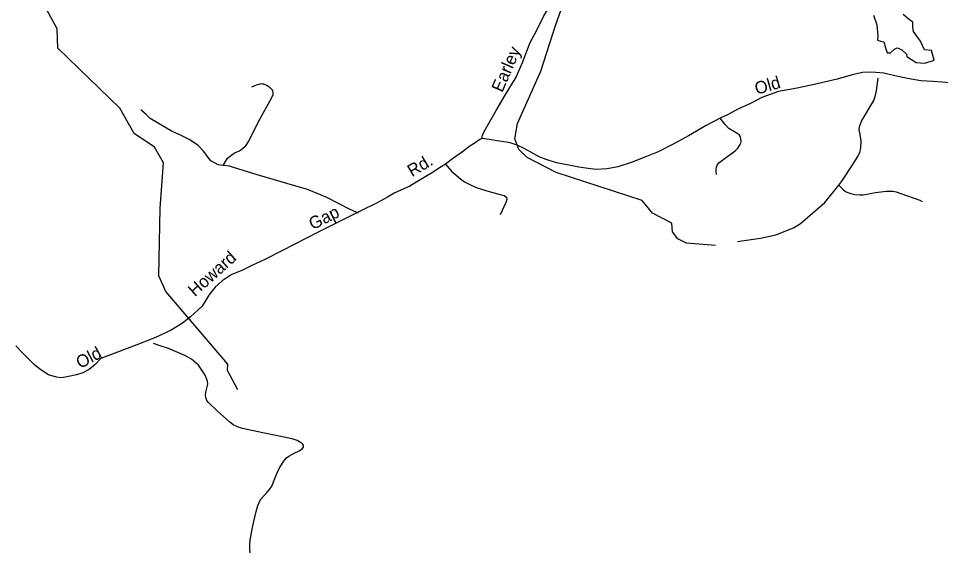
# Model space of a CAD drawing. Extents: x 990631 to 1056237, y 535999 to 585651.
# Drawn here: x 1014890 to 1021960, y 555422 to 559461 of the extents above; entities that cross this region are included whole.
import ezdxf

# ---------------------------------------------------------------- set-up
doc = ezdxf.new("R2010")
doc.units = 0
for name, color, linetype in [('Exist Hydrographic Creek Single Shore', 7, 'Continuous'), ('Exist Hydrographic Pond Over 1500 Sq Ft', 7, 'Continuous'), ('Exist Road Non-System Type 51', 7, 'Continuous'), ('Exist Road Secondary Type 41 Attributed', 7, 'Continuous'), ('Exist Road Secondary Type 51 Attributed', 7, 'Continuous'), ('Exist Road Secondary Type 51 Label', 7, 'Continuous')]:
    doc.layers.add(name, color=color, linetype=linetype)

msp = doc.modelspace()

# ---------------------------------------------------------------- linework, layer by layer
at = {"layer": 'Exist Hydrographic Creek Single Shore'}
for points in [[(1016571.4, 556616.2), (1016492.9, 556762.2), (1016494.5, 556811.4), (1016021.2, 557369), (1015966.6, 557488.3), (1015975.7, 558006.6), (1016003.6, 558354), (1015932.7, 558473.5), (1015777.9, 558578.4), (1015667.7, 558774.2), (1015191, 559233.5), (1015187.6, 559381.3), (1015109.1, 559527.2), (1015083.9, 559770.6), (1014986.1, 560090.9), (1014907.6, 560243.5), (1014912.8, 560391), (1015271.4, 560895.8), (1015405.6, 561168.8), (1015417.6, 561276.8), (1015082.1, 561720), (1014955.8, 561912.5), (1014924.7, 562002.2)], [(1016571.4, 556616.2), (1016492.9, 556762.2), (1016494.5, 556811.4), (1016021.2, 557369), (1015966.6, 557488.3), (1015975.7, 558006.6), (1016003.6, 558354), (1015932.7, 558473.5), (1015777.9, 558578.4), (1015667.7, 558774.2), (1015191, 559233.5), (1015187.6, 559381.3), (1015109.1, 559527.2), (1015083.9, 559770.6), (1014986.1, 560090.9), (1014907.6, 560243.5), (1014912.8, 560391), (1015271.4, 560895.8), (1015405.6, 561168.8), (1015417.6, 561276.8), (1015082.1, 561720), (1014955.8, 561912.5), (1014924.7, 562002.2)], [(1020235.4, 557720.5), (1020011, 557738.2), (1019945.4, 557772.3), (1019905.5, 557825.6), (1019899.3, 557891.4), (1019751.9, 557969.8), (1019671.6, 558066.6), (1019011.7, 558280.1), (1018790.5, 558396.1), (1018725.7, 558456.6), (1018695.2, 558539.2), (1018715.7, 558657), (1018895.9, 559057), (1019007.6, 559405.9), (1019191.5, 559924)], [(1020235.4, 557720.5), (1020011, 557738.2), (1019945.4, 557772.3), (1019905.5, 557825.6), (1019899.3, 557891.4), (1019751.9, 557969.8), (1019671.6, 558066.6), (1019011.7, 558280.1), (1018790.5, 558396.1), (1018725.7, 558456.6), (1018695.2, 558539.2), (1018715.7, 558657), (1018895.9, 559057), (1019007.6, 559405.9), (1019191.5, 559924)]]:
    msp.add_lwpolyline(points, dxfattribs=at)
at = {"layer": 'Exist Hydrographic Pond Over 1500 Sq Ft'}
msp.add_lwpolyline([(1021446.8, 559486.9), (1021471.9, 559411.6), (1021480.3, 559323.8), (1021476.1, 559294.5), (1021501.2, 559286.2), (1021526.3, 559282), (1021538.8, 559236), (1021551.3, 559198.3), (1021576.4, 559198.3), (1021609.9, 559227.6), (1021630.8, 559236), (1021664.2, 559219.2), (1021697.6, 559185.8), (1021701.8, 559169.1), (1021772.9, 559123.1), (1021839.8, 559118.9), (1021910.8, 559139.8), (1021898.3, 559185.8), (1021889.9, 559215.1), (1021835.6, 559219.2), (1021806.3, 559286.2), (1021752, 559361.4), (1021747.8, 559394.9), (1021747.8, 559432.5), (1021722.7, 559449.2), (1021672.6, 559491.1)], dxfattribs=at)
at = {"layer": 'Exist Road Non-System Type 51'}
for points in [[(1016459.9, 558333.8), (1016491.8, 558390.8), (1016547.3, 558431.1), (1016583.8, 558445.7), (1016633, 558484.2), (1016656.3, 558521.5), (1016707.8, 558623.9), (1016741.9, 558688.6), (1016805.9, 558804.6), (1016833.5, 558855.8), (1016842.3, 558877.5), (1016842.9, 558893.5), (1016839.4, 558907.5), (1016831.6, 558917.9), (1016820, 558928.3), (1016804.4, 558938.9), (1016794.5, 558947.1), (1016770.9, 558955.9), (1016759, 558958.4), (1016749, 558958.6), (1016732.9, 558955.3), (1016712.6, 558949.9), (1016678.1, 558935)], [(1021180, 558184.3), (1021203, 558213.7), (1021283.1, 558335.1), (1021325.3, 558403.7), (1021342.6, 558441.1), (1021347.7, 558473), (1021351.2, 558520.8), (1021342.8, 558571.2), (1021336.2, 558607.5), (1021338.8, 558629.3), (1021354.3, 558674.8), (1021375.7, 558712.1), (1021426.4, 558794.6), (1021447.7, 558831.9), (1021458.8, 558863.5), (1021468.2, 558905.1), (1021481.4, 559002.9)], [(1016459.9, 558333.8), (1016422, 558339.2), (1016398.4, 558351.9), (1016365, 558369.1), (1016343.9, 558395.8), (1016326.8, 558420.3), (1016305.5, 558445.2), (1016266.9, 558486.4), (1016204.4, 558530.4), (1016127.5, 558569.2), (1016068.4, 558595.2), (1015899.6, 558694.8), (1015868.6, 558723.9), (1015827.7, 558759.3)], [(1020242, 558265.7), (1020238.9, 558289.7), (1020239.4, 558305.7), (1020241.9, 558321.7), (1020248.4, 558337.6), (1020258.9, 558353.2), (1020328.8, 558405), (1020365.8, 558431.6), (1020388.3, 558449), (1020406.9, 558466.4), (1020419.5, 558486), (1020428.1, 558505.6), (1020430.8, 558521.6), (1020429.3, 558537.6), (1020425.8, 558553.7), (1020418.3, 558566), (1020406.5, 558576.5), (1020337.9, 558618.7), (1020307, 558651.7), (1020270.5, 558697)], [(1017498.4, 557968.9), (1017433.4, 557997.3), (1017248.4, 558091.4), (1017106.2, 558150.1), (1017009.1, 558177.5), (1016737.6, 558258.6), (1016612.7, 558294.7), (1016531.5, 558321.6), (1016507.8, 558328.2), (1016459.9, 558333.8)], [(1018165.4, 558345), (1018211.5, 558289.5), (1018279.7, 558231.1), (1018310.9, 558208), (1018360.2, 558182.4), (1018407.4, 558162.9), (1018498.7, 558135.8), (1018583.8, 558110.9), (1018613.7, 558103.9), (1018631.2, 558091.3), (1018634.6, 558073.2), (1018625.8, 558049.4), (1018584.6, 557954.8)], [(1021180, 558184.3), (1021203, 558213.7), (1021249.1, 558283.5)], [(1020403.1, 557752.1), (1020453.3, 557760.3), (1020580, 557778.1), (1020697, 557802.1), (1020832.7, 557855.6), (1020886, 557890), (1021071.5, 558049.9), (1021148.6, 558145.3), (1021180, 558184.3)], [(1021180, 558184.3), (1021214.7, 558147.2), (1021232.4, 558134.7), (1021248, 558126.1), (1021249.1, 558125.8)], [(1021180, 558184.3), (1021214.7, 558147.2), (1021232.4, 558134.7), (1021248, 558126.1), (1021271.9, 558119.2), (1021303.6, 558112.2), (1021341.5, 558108.8), (1021367.5, 558108.1), (1021462.1, 558126.8), (1021542.5, 558136.2), (1021566.6, 558137.5), (1021594.6, 558136.5), (1021618.5, 558131.7), (1021656.1, 558120.5), (1021800.4, 558067.6), (1021818.3, 558059)], [(1016666, 555328.9), (1016665.2, 555427.1), (1016666.5, 555465.1), (1016688.1, 555572.3), (1016711.7, 555683.7), (1016725.3, 555729.2), (1016744.8, 555774.6), (1016796.7, 555831), (1016815.3, 555850.4), (1016832.3, 555877.7), (1016856.3, 555937), (1016875.9, 555984.5), (1016890.9, 556018), (1016930.9, 556076.6), (1016945.5, 556094.1), (1016962, 556107.6), (1017004.8, 556130.1), (1017041.4, 556149), (1017068, 556166.2), (1017076.4, 556175.9), (1017076.8, 556187.9), (1017067.3, 556200.3), (1017053.7, 556212.5), (1017026, 556227.5), (1016988.4, 556238.9), (1016763.9, 556286.4), (1016608.9, 556319.6), (1016569.1, 556331), (1016537.6, 556346), (1016508.5, 556371), (1016415.1, 556452.1), (1016347.3, 556518.5), (1016335.8, 556534.7), (1016328.3, 556549.1), (1016325.1, 556571.2), (1016327.8, 556597.1), (1016342.1, 556658.6), (1016338.8, 556682.7), (1016322.3, 556727.5), (1016270.8, 556805.1), (1016216.3, 556851), (1016165.3, 556878.7), (1016040.9, 556931), (1015977.5, 556951.1), (1015926.1, 556970.7)]]:
    msp.add_lwpolyline(points, dxfattribs=at)
at = {"layer": 'Exist Road Secondary Type 41 Attributed'}
msp.add_lwpolyline([(1018444, 558541.8), (1018444.5, 558553.8), (1018448.9, 558565.8), (1018461.9, 558595.3), (1018553.4, 558756.3), (1018614.9, 558860.3), (1018705.9, 559009.5), (1018755.7, 559123.9), (1018814.7, 559276), (1018864.1, 559370.4), (1018917.7, 559480.6), (1019002.3, 559617.9), (1019091.2, 559759.2), (1019118.8, 559812.2), (1019122.6, 559862.2), (1019120.2, 559912.2), (1019098.2, 559970.9), (1019006, 560090.2), (1018911, 560183.4), (1018890.1, 560214.2), (1018852.1, 560215.4), (1018800.4, 560221.2), (1018718.5, 560225.9), (1018705.5, 560227.9)], dxfattribs=at)
at = {"layer": 'Exist Road Secondary Type 51 Attributed'}
for points in [[(1022036.8, 558967.3), (1021904.2, 558976.3), (1021809.7, 558983), (1021706.3, 559001), (1021609.5, 559021.3), (1021524.1, 559041.5), (1021431.9, 559048.3), (1021362.2, 559046), (1021283.5, 559028), (1021166.5, 558996.5), (1021013.6, 558960.5), (1020860.7, 558926.8), (1020716.7, 558899.7), (1020590.8, 558854.7), (1020502.4, 558809.4), (1020404.9, 558764.6), (1020327.4, 558721.1), (1020270.5, 558697), (1020162.5, 558640.6), (1020027.7, 558561.1), (1019915.6, 558500.7), (1019795.5, 558438.7), (1019704.2, 558401.8), (1019594.7, 558359.4), (1019485.6, 558325), (1019405, 558309.6), (1019320.7, 558304.5), (1019259, 558310.5), (1019187.2, 558321), (1019109.7, 558335.5), (1019016.2, 558354.6), (1018937.1, 558379.2), (1018881.7, 558401.2), (1018842.4, 558424.6), (1018767.8, 558465.1), (1018714.7, 558490.8), (1018661, 558506.7), (1018629.3, 558511.7), (1018561.5, 558521.9), (1018501.9, 558533.9), (1018444, 558541.8)], [(1021249.1, 559018.8), (1021166.5, 558996.5), (1021013.6, 558960.5), (1020860.7, 558926.8), (1020716.7, 558899.7), (1020590.8, 558854.7), (1020502.4, 558809.4), (1020404.9, 558764.6), (1020327.4, 558721.1), (1020270.5, 558697), (1020162.5, 558640.6), (1020027.7, 558561.1), (1019915.6, 558500.7), (1019795.5, 558438.7), (1019704.2, 558401.8), (1019594.7, 558359.4), (1019485.6, 558325), (1019405, 558309.6), (1019320.7, 558304.5), (1019259, 558310.5), (1019187.2, 558321), (1019109.7, 558335.5), (1019016.2, 558354.6), (1018937.1, 558379.2), (1018881.7, 558401.2), (1018842.4, 558424.6), (1018767.8, 558465.1), (1018714.7, 558490.8), (1018661, 558506.7), (1018629.3, 558511.7), (1018561.5, 558521.9), (1018501.9, 558533.9), (1018444, 558541.8)], [(1018444, 558541.8), (1018427.9, 558534.4), (1018384.9, 558503.8), (1018352, 558482.9), (1018294.5, 558438.8), (1018218.8, 558385.3), (1018165.4, 558345), (1018130.6, 558324.1), (1018102, 558305.1)], [(1018102, 558305.1), (1018069.3, 558282.1), (1017944.8, 558208.2), (1017891.5, 558176.1), (1017771.6, 558122.1), (1017720.8, 558091.7), (1017635, 558046.4), (1017519.6, 557989.7), (1017413.9, 557934.8), (1017181.8, 557819.4), (1016915.4, 557683.3), (1016779.5, 557614.6), (1016680.6, 557567.9), (1016609.2, 557530.8), (1016520, 557495.1), (1016452.7, 557451.1), (1016399.1, 557401.7), (1016351.1, 557339.8), (1016298.9, 557257.4), (1016208.3, 557175), (1016147.9, 557126.9), (1016061.3, 557071.9), (1015941.9, 557015.6), (1015797.7, 556960.6), (1015650.8, 556904.3), (1015523.1, 556854.8), (1015477.8, 556808.1), (1015432.5, 556771), (1015384.4, 556744.9), (1015336.3, 556731.2), (1015274.5, 556716.1), (1015219.6, 556706.4), (1015182.5, 556711.9), (1015119.4, 556731.2), (1015063.1, 556768.3), (1015017.8, 556802.6), (1014972.5, 556846.6), (1014920.3, 556897.4), (1014869.5, 556952.4)]]:
    msp.add_lwpolyline(points, dxfattribs=at)

# ---------------------------------------------------------------- texts
at = {"layer": 'Exist Road Secondary Type 51 Label'}
for s, rotation, p in [('Earley', 66.5156, (1018599.7, 558888.4)), ('Earley', 66.5156, (1018599.7, 558888.4)), ('Old', 16.23539, (1020550.8, 558875.2)), ('Old', 16.23539, (1020550.8, 558875.2)), ('Rd.', 30.69115, (1017907.9, 558243.5)), ('Rd.', 30.69115, (1017907.9, 558243.5)), ('Gap', 26.85999, (1017146.6, 557837.7)), ('Gap', 26.85999, (1017146.6, 557837.7)), ('Howard', 41.74499, (1016242.9, 557324.3)), ('Howard', 41.74499, (1016242.9, 557324.3)), ('Old', 28.04663, (1015363.4, 556774.6)), ('Old', 28.04663, (1015363.4, 556774.6))]:
    msp.add_text(s, height=95, rotation=rotation, dxfattribs=at).set_placement(p)

doc.saveas('drawing.dxf')
